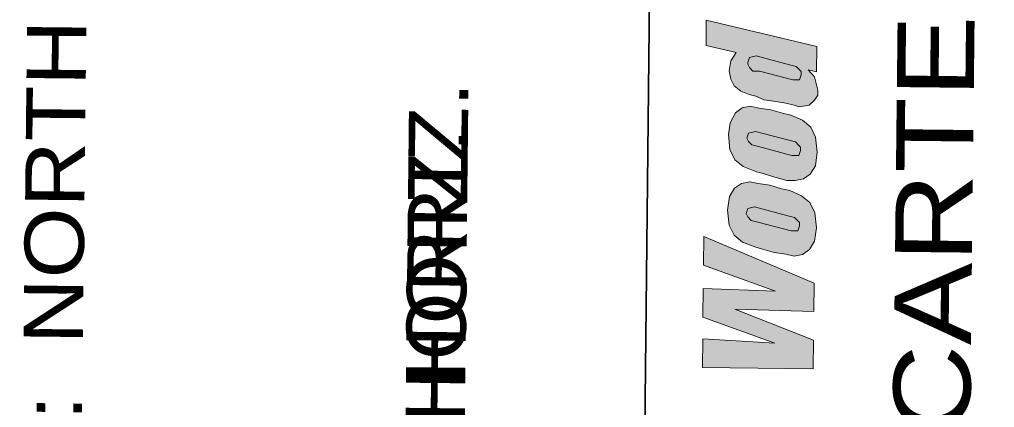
# Model space of a CAD drawing. Extents: x 2356576 to 2377878, y 6966390 to 6990634.
# Drawn here: x 2366724.3 to 2366947.6, y 6989974.5 to 6990063.3 of the extents above; entities that cross this region are included whole.
import ezdxf

# ---------------------------------------------------------------- set-up
doc = ezdxf.new("R2010")
doc.units = 0
doc.header["$LTSCALE"] = 7.1
doc.layers.add('19', color=7, linetype='Continuous', lineweight=13)
doc.layers.add('8', color=7, linetype='Continuous', lineweight=13)

msp = doc.modelspace()

# ---------------------------------------------------------------- hatches: boundary and pattern name
at = {"layer": '19'}
for points in [[(2366906.846, 6990057.071), (2366881.568, 6990063.113), (2366881.504, 6990057.353), (2366888.398, 6990055.739), (2366887.224, 6990053.833), (2366886.816, 6990051.533), (2366887.178, 6990049.609), (2366887.928, 6990048.065), (2366889.452, 6990046.895), (2366891.364, 6990046.105), (2366892.894, 6990045.705), (2366894.806, 6990044.915), (2366897.49, 6990044.501), (2366899.79, 6990044.091), (2366901.706, 6990043.687), (2366902.854, 6990043.291), (2366905.162, 6990043.647), (2366906.326, 6990044.787), (2366907.108, 6990045.931), (2366907.12, 6990047.083), (2366906.752, 6990048.623), (2366906.386, 6990050.163), (2366905.626, 6990050.941), (2366904.868, 6990051.717), (2366906.782, 6990051.311)], [(2366891.06, 6990053.407), (2366891.456, 6990054.555), (2366892.996, 6990054.921), (2366900.656, 6990052.915), (2366902.188, 6990052.515), (2366902.948, 6990051.739), (2366903.328, 6990051.351), (2366903.318, 6990050.583), (2366902.922, 6990049.435), (2366901.386, 6990049.451), (2366893.726, 6990051.457), (2366892.19, 6990051.473), (2366891.432, 6990052.251), (2366891.056, 6990053.023)], [(2366900.912, 6990041.391), (2366898.996, 6990041.797), (2366896.316, 6990042.595), (2366893.632, 6990043.007), (2366891.716, 6990043.413), (2366889.792, 6990043.051), (2366888.244, 6990041.915), (2366887.068, 6990039.625), (2366886.652, 6990036.941), (2366886.998, 6990033.481), (2366888.124, 6990031.165), (2366890.028, 6990029.607), (2366893.086, 6990028.421), (2366894.618, 6990028.019), (2366897.298, 6990027.221), (2366899.978, 6990026.423), (2366901.898, 6990026.403), (2366903.822, 6990026.765), (2366905.37, 6990027.899), (2366906.544, 6990029.807), (2366906.962, 6990032.875), (2366906.616, 6990036.335), (2366905.49, 6990038.653), (2366903.588, 6990040.209)], [(2366890.868, 6990036.127), (2366891.264, 6990037.275), (2366892.804, 6990037.641), (2366900.464, 6990035.635), (2366901.996, 6990035.235), (2366902.756, 6990034.459), (2366903.136, 6990034.071), (2366903.126, 6990033.303), (2366902.73, 6990032.155), (2366901.194, 6990032.171), (2366893.534, 6990034.177), (2366892.004, 6990034.577), (2366891.244, 6990035.355)], [(2366900.72, 6990024.111), (2366898.804, 6990024.517), (2366896.126, 6990025.315), (2366893.44, 6990025.729), (2366891.526, 6990026.133), (2366889.6, 6990025.771), (2366888.052, 6990024.637), (2366886.88, 6990022.729), (2366886.46, 6990019.661), (2366886.806, 6990016.201), (2366887.932, 6990013.885), (2366889.836, 6990012.327), (2366892.896, 6990011.141), (2366894.426, 6990010.739), (2366897.106, 6990009.943), (2366899.79, 6990009.527), (2366901.706, 6990009.123), (2366903.63, 6990009.485), (2366905.178, 6990010.621), (2366906.352, 6990012.529), (2366906.77, 6990015.595), (2366906.424, 6990019.055), (2366905.298, 6990021.373), (2366903.396, 6990022.929)], [(2366890.676, 6990018.847), (2366891.072, 6990019.995), (2366892.614, 6990020.361), (2366900.272, 6990018.355), (2366901.804, 6990017.955), (2366902.564, 6990017.179), (2366902.944, 6990016.791), (2366902.934, 6990016.023), (2366902.538, 6990014.875), (2366901.002, 6990014.891), (2366893.344, 6990016.897), (2366891.812, 6990017.299), (2366891.052, 6990018.075)], [(2366880.944, 6990007.049), (2366881.016, 6990013.577), (2366906.246, 6990002.927), (2366906.172, 6989996.401), (2366888.13, 6989996.985), (2366906.1, 6989989.871), (2366906.028, 6989983.345), (2366880.684, 6989983.627), (2366880.756, 6989990.153), (2366897.26, 6989989.203), (2366880.812, 6989995.147), (2366880.884, 6990001.673), (2366897.392, 6990001.107)]]:
    msp.add_hatch(color=256, dxfattribs=at).paths.add_polyline_path(points)
at = {"layer": '8'}
for points in [[(2366906.846, 6990057.071), (2366881.568, 6990063.113), (2366881.504, 6990057.353), (2366888.398, 6990055.739), (2366887.224, 6990053.833), (2366886.816, 6990051.533), (2366887.178, 6990049.609), (2366887.928, 6990048.065), (2366889.452, 6990046.895), (2366891.364, 6990046.105), (2366892.894, 6990045.705), (2366894.806, 6990044.915), (2366897.49, 6990044.501), (2366899.79, 6990044.091), (2366901.706, 6990043.687), (2366902.854, 6990043.291), (2366905.162, 6990043.647), (2366906.326, 6990044.787), (2366907.108, 6990045.931), (2366907.12, 6990047.083), (2366906.752, 6990048.623), (2366906.386, 6990050.163), (2366905.626, 6990050.941), (2366904.868, 6990051.717), (2366906.782, 6990051.311)], [(2366891.06, 6990053.407), (2366891.456, 6990054.555), (2366892.996, 6990054.921), (2366900.656, 6990052.915), (2366902.188, 6990052.515), (2366902.948, 6990051.739), (2366903.328, 6990051.351), (2366903.318, 6990050.583), (2366902.922, 6990049.435), (2366901.386, 6990049.451), (2366893.726, 6990051.457), (2366892.19, 6990051.473), (2366891.432, 6990052.251), (2366891.056, 6990053.023)], [(2366900.912, 6990041.391), (2366898.996, 6990041.797), (2366896.316, 6990042.595), (2366893.632, 6990043.007), (2366891.716, 6990043.413), (2366889.792, 6990043.051), (2366888.244, 6990041.915), (2366887.068, 6990039.625), (2366886.652, 6990036.941), (2366886.998, 6990033.481), (2366888.124, 6990031.165), (2366890.028, 6990029.607), (2366893.086, 6990028.421), (2366894.618, 6990028.019), (2366897.298, 6990027.221), (2366899.978, 6990026.423), (2366901.898, 6990026.403), (2366903.822, 6990026.765), (2366905.37, 6990027.899), (2366906.544, 6990029.807), (2366906.962, 6990032.875), (2366906.616, 6990036.335), (2366905.49, 6990038.653), (2366903.588, 6990040.209)], [(2366890.868, 6990036.127), (2366891.264, 6990037.275), (2366892.804, 6990037.641), (2366900.464, 6990035.635), (2366901.996, 6990035.235), (2366902.756, 6990034.459), (2366903.136, 6990034.071), (2366903.126, 6990033.303), (2366902.73, 6990032.155), (2366901.194, 6990032.171), (2366893.534, 6990034.177), (2366892.004, 6990034.577), (2366891.244, 6990035.355)], [(2366900.72, 6990024.111), (2366898.804, 6990024.517), (2366896.126, 6990025.315), (2366893.44, 6990025.729), (2366891.526, 6990026.133), (2366889.6, 6990025.771), (2366888.052, 6990024.637), (2366886.88, 6990022.729), (2366886.46, 6990019.661), (2366886.806, 6990016.201), (2366887.932, 6990013.885), (2366889.836, 6990012.327), (2366892.896, 6990011.141), (2366894.426, 6990010.739), (2366897.106, 6990009.943), (2366899.79, 6990009.527), (2366901.706, 6990009.123), (2366903.63, 6990009.485), (2366905.178, 6990010.621), (2366906.352, 6990012.529), (2366906.77, 6990015.595), (2366906.424, 6990019.055), (2366905.298, 6990021.373), (2366903.396, 6990022.929)], [(2366890.676, 6990018.847), (2366891.072, 6990019.995), (2366892.614, 6990020.361), (2366900.272, 6990018.355), (2366901.804, 6990017.955), (2366902.564, 6990017.179), (2366902.944, 6990016.791), (2366902.934, 6990016.023), (2366902.538, 6990014.875), (2366901.002, 6990014.891), (2366893.344, 6990016.897), (2366891.812, 6990017.299), (2366891.052, 6990018.075)], [(2366880.944, 6990007.049), (2366881.016, 6990013.577), (2366906.246, 6990002.927), (2366906.172, 6989996.401), (2366888.13, 6989996.985), (2366906.1, 6989989.871), (2366906.028, 6989983.345), (2366880.684, 6989983.627), (2366880.756, 6989990.153), (2366897.26, 6989989.203), (2366880.812, 6989995.147), (2366880.884, 6990001.673), (2366897.392, 6990001.107)]]:
    msp.add_hatch(color=256, dxfattribs=at).paths.add_polyline_path(points)

# ---------------------------------------------------------------- linework, layer by layer
at = {"layer": '19', "lineweight": 35}
msp.add_line((2366874.428, 6990595.923), (2366865.462, 6989788.709), dxfattribs=at)
at = {"layer": '19'}
for points in [[(2366906.846, 6990057.071), (2366881.568, 6990063.113), (2366881.504, 6990057.353), (2366888.398, 6990055.739), (2366887.224, 6990053.833), (2366886.816, 6990051.533), (2366887.178, 6990049.609), (2366887.928, 6990048.065), (2366889.452, 6990046.895), (2366891.364, 6990046.105), (2366892.894, 6990045.705), (2366894.806, 6990044.915), (2366897.49, 6990044.501), (2366899.79, 6990044.091), (2366901.706, 6990043.687), (2366902.854, 6990043.291), (2366905.162, 6990043.647), (2366906.326, 6990044.787), (2366907.108, 6990045.931), (2366907.12, 6990047.083), (2366906.752, 6990048.623), (2366906.386, 6990050.163), (2366905.626, 6990050.941), (2366904.868, 6990051.717), (2366906.782, 6990051.311)], [(2366891.06, 6990053.407), (2366891.456, 6990054.555), (2366892.996, 6990054.921), (2366900.656, 6990052.915), (2366902.188, 6990052.515), (2366902.948, 6990051.739), (2366903.328, 6990051.351), (2366903.318, 6990050.583), (2366902.922, 6990049.435), (2366901.386, 6990049.451), (2366893.726, 6990051.457), (2366892.19, 6990051.473), (2366891.432, 6990052.251), (2366891.056, 6990053.023)], [(2366900.912, 6990041.391), (2366898.996, 6990041.797), (2366896.316, 6990042.595), (2366893.632, 6990043.007), (2366891.716, 6990043.413), (2366889.792, 6990043.051), (2366888.244, 6990041.915), (2366887.068, 6990039.625), (2366886.652, 6990036.941), (2366886.998, 6990033.481), (2366888.124, 6990031.165), (2366890.028, 6990029.607), (2366893.086, 6990028.421), (2366894.618, 6990028.019), (2366897.298, 6990027.221), (2366899.978, 6990026.423), (2366901.898, 6990026.403), (2366903.822, 6990026.765), (2366905.37, 6990027.899), (2366906.544, 6990029.807), (2366906.962, 6990032.875), (2366906.616, 6990036.335), (2366905.49, 6990038.653), (2366903.588, 6990040.209)], [(2366890.868, 6990036.127), (2366891.264, 6990037.275), (2366892.804, 6990037.641), (2366900.464, 6990035.635), (2366901.996, 6990035.235), (2366902.756, 6990034.459), (2366903.136, 6990034.071), (2366903.126, 6990033.303), (2366902.73, 6990032.155), (2366901.194, 6990032.171), (2366893.534, 6990034.177), (2366892.004, 6990034.577), (2366891.244, 6990035.355)], [(2366900.72, 6990024.111), (2366898.804, 6990024.517), (2366896.126, 6990025.315), (2366893.44, 6990025.729), (2366891.526, 6990026.133), (2366889.6, 6990025.771), (2366888.052, 6990024.637), (2366886.88, 6990022.729), (2366886.46, 6990019.661), (2366886.806, 6990016.201), (2366887.932, 6990013.885), (2366889.836, 6990012.327), (2366892.896, 6990011.141), (2366894.426, 6990010.739), (2366897.106, 6990009.943), (2366899.79, 6990009.527), (2366901.706, 6990009.123), (2366903.63, 6990009.485), (2366905.178, 6990010.621), (2366906.352, 6990012.529), (2366906.77, 6990015.595), (2366906.424, 6990019.055), (2366905.298, 6990021.373), (2366903.396, 6990022.929)], [(2366890.676, 6990018.847), (2366891.072, 6990019.995), (2366892.614, 6990020.361), (2366900.272, 6990018.355), (2366901.804, 6990017.955), (2366902.564, 6990017.179), (2366902.944, 6990016.791), (2366902.934, 6990016.023), (2366902.538, 6990014.875), (2366901.002, 6990014.891), (2366893.344, 6990016.897), (2366891.812, 6990017.299), (2366891.052, 6990018.075)], [(2366880.944, 6990007.049), (2366881.016, 6990013.577), (2366906.246, 6990002.927), (2366906.172, 6989996.401), (2366888.13, 6989996.985), (2366906.1, 6989989.871), (2366906.028, 6989983.345), (2366880.684, 6989983.627), (2366880.756, 6989990.153), (2366897.26, 6989989.203), (2366880.812, 6989995.147), (2366880.884, 6990001.673), (2366897.392, 6990001.107)]]:
    msp.add_lwpolyline(points, close=True, dxfattribs=at)
at = {"layer": '8', "lineweight": 35}
msp.add_line((2366874.428, 6990595.923), (2366865.462, 6989788.709), dxfattribs=at)
at = {"layer": '8'}
for points in [[(2366906.846, 6990057.071), (2366881.568, 6990063.113), (2366881.504, 6990057.353), (2366888.398, 6990055.739), (2366887.224, 6990053.833), (2366886.816, 6990051.533), (2366887.178, 6990049.609), (2366887.928, 6990048.065), (2366889.452, 6990046.895), (2366891.364, 6990046.105), (2366892.894, 6990045.705), (2366894.806, 6990044.915), (2366897.49, 6990044.501), (2366899.79, 6990044.091), (2366901.706, 6990043.687), (2366902.854, 6990043.291), (2366905.162, 6990043.647), (2366906.326, 6990044.787), (2366907.108, 6990045.931), (2366907.12, 6990047.083), (2366906.752, 6990048.623), (2366906.386, 6990050.163), (2366905.626, 6990050.941), (2366904.868, 6990051.717), (2366906.782, 6990051.311)], [(2366891.06, 6990053.407), (2366891.456, 6990054.555), (2366892.996, 6990054.921), (2366900.656, 6990052.915), (2366902.188, 6990052.515), (2366902.948, 6990051.739), (2366903.328, 6990051.351), (2366903.318, 6990050.583), (2366902.922, 6990049.435), (2366901.386, 6990049.451), (2366893.726, 6990051.457), (2366892.19, 6990051.473), (2366891.432, 6990052.251), (2366891.056, 6990053.023)], [(2366900.912, 6990041.391), (2366898.996, 6990041.797), (2366896.316, 6990042.595), (2366893.632, 6990043.007), (2366891.716, 6990043.413), (2366889.792, 6990043.051), (2366888.244, 6990041.915), (2366887.068, 6990039.625), (2366886.652, 6990036.941), (2366886.998, 6990033.481), (2366888.124, 6990031.165), (2366890.028, 6990029.607), (2366893.086, 6990028.421), (2366894.618, 6990028.019), (2366897.298, 6990027.221), (2366899.978, 6990026.423), (2366901.898, 6990026.403), (2366903.822, 6990026.765), (2366905.37, 6990027.899), (2366906.544, 6990029.807), (2366906.962, 6990032.875), (2366906.616, 6990036.335), (2366905.49, 6990038.653), (2366903.588, 6990040.209)], [(2366890.868, 6990036.127), (2366891.264, 6990037.275), (2366892.804, 6990037.641), (2366900.464, 6990035.635), (2366901.996, 6990035.235), (2366902.756, 6990034.459), (2366903.136, 6990034.071), (2366903.126, 6990033.303), (2366902.73, 6990032.155), (2366901.194, 6990032.171), (2366893.534, 6990034.177), (2366892.004, 6990034.577), (2366891.244, 6990035.355)], [(2366900.72, 6990024.111), (2366898.804, 6990024.517), (2366896.126, 6990025.315), (2366893.44, 6990025.729), (2366891.526, 6990026.133), (2366889.6, 6990025.771), (2366888.052, 6990024.637), (2366886.88, 6990022.729), (2366886.46, 6990019.661), (2366886.806, 6990016.201), (2366887.932, 6990013.885), (2366889.836, 6990012.327), (2366892.896, 6990011.141), (2366894.426, 6990010.739), (2366897.106, 6990009.943), (2366899.79, 6990009.527), (2366901.706, 6990009.123), (2366903.63, 6990009.485), (2366905.178, 6990010.621), (2366906.352, 6990012.529), (2366906.77, 6990015.595), (2366906.424, 6990019.055), (2366905.298, 6990021.373), (2366903.396, 6990022.929)], [(2366890.676, 6990018.847), (2366891.072, 6990019.995), (2366892.614, 6990020.361), (2366900.272, 6990018.355), (2366901.804, 6990017.955), (2366902.564, 6990017.179), (2366902.944, 6990016.791), (2366902.934, 6990016.023), (2366902.538, 6990014.875), (2366901.002, 6990014.891), (2366893.344, 6990016.897), (2366891.812, 6990017.299), (2366891.052, 6990018.075)], [(2366880.944, 6990007.049), (2366881.016, 6990013.577), (2366906.246, 6990002.927), (2366906.172, 6989996.401), (2366888.13, 6989996.985), (2366906.1, 6989989.871), (2366906.028, 6989983.345), (2366880.684, 6989983.627), (2366880.756, 6989990.153), (2366897.26, 6989989.203), (2366880.812, 6989995.147), (2366880.884, 6990001.673), (2366897.392, 6990001.107)]]:
    msp.add_lwpolyline(points, close=True, dxfattribs=at)

# ---------------------------------------------------------------- texts
at = {"layer": '19'}
for s, height, width, p in [('LIMITS:  NORTH INTERCHANGE SH 121 TO RANDOL MILL ROAD', 13.58, 1.15, (2366737.852, 6989904.165)), ('4100 AMON CARTER BLVD., ', 17.63, 1.2, (2366940.144, 6989804.777)), ('SCALE:  1" = 100\' HORIZ.', 13.58, 1.1, (2366824.416, 6989804.941))]:
    msp.add_text(s, height=height, rotation=89.364, dxfattribs=dict(at, width=width)).set_placement(p)
at = {"layer": '8'}
for s, height, width, p in [('LIMITS:  NORTH INTERCHANGE SH 121 TO RANDOL MILL ROAD', 13.58, 1.15, (2366737.852, 6989904.165)), ('4100 AMON CARTER BLVD., ', 17.63, 1.2, (2366940.144, 6989804.777)), ('SCALE:  1" = 200\' HORIZ.', 13.58, 1.15, (2366824.416, 6989804.941))]:
    msp.add_text(s, height=height, rotation=89.364, dxfattribs=dict(at, width=width)).set_placement(p)

doc.saveas('drawing.dxf')
